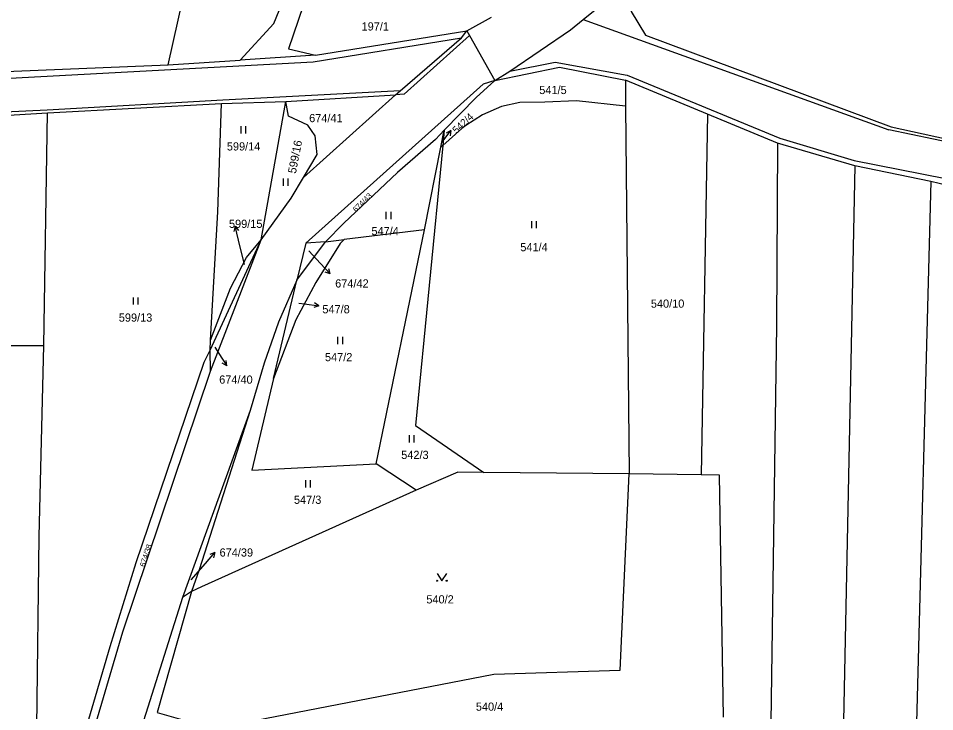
# Model space of a CAD drawing. Extents: x -747333 to -743907, y -1134120 to -1130051.
# Drawn here: x -746832.8 to -746642.5, y -1132407.1 to -1132263.2 of the extents above; entities that cross this region are included whole.
import ezdxf

# ---------------------------------------------------------------- set-up
doc = ezdxf.new("R2010")
doc.units = 0
for name, color, linetype in [('Hranice parcel', 7, 'Continuous'), ('Parcelní čísla', 7, 'Continuous'), ('Pop  PČ popisy', 7, 'Continuous'), ('Vnitřní kresba', 7, 'Continuous'), ('Značky kultur', 7, 'Continuous')]:
    doc.layers.add(name, color=color, linetype=linetype)

msp = doc.modelspace()

# ---------------------------------------------------------------- linework, layer by layer
at = {"layer": 'Hranice parcel'}
for p, q in [((-746801.64, -1132272.79), (-746795.83, -1132246.75)), ((-746779.69, -1132264.25), (-746775.72, -1132254.29)), ((-746786.69, -1132271.84), (-746779.69, -1132264.25)), ((-746739.61, -1132265.77), (-746734.54, -1132262.91)), ((-746771.04, -1132270.84), (-746739.61, -1132265.77)), ((-746801.64, -1132272.79), (-746786.69, -1132271.84)), ((-746771.04, -1132270.84), (-746786.69, -1132271.84)), ((-746841.63, -1132274.45), (-746801.64, -1132272.79)), ((-746706.71, -1132276.02), (-746706.66, -1132281.38)), ((-746689.65, -1132283.05), (-746706.71, -1132276.02)), ((-746777.2, -1132280.46), (-746754.45, -1132279.02)), ((-746773.55, -1132296.22), (-746754.45, -1132279.02)), ((-746826.69, -1132282.8), (-746790.54, -1132280.83)), ((-746790.54, -1132280.83), (-746777.2, -1132280.46)), ((-746782.33, -1132309.15), (-746777.2, -1132280.46)), ((-746706.66, -1132281.38), (-746716.86, -1132280.27)), ((-746706.66, -1132281.38), (-746705.91, -1132357.75)), ((-746843.01, -1132283.74), (-746826.69, -1132282.8)), ((-746827.45, -1132331.11), (-746826.69, -1132282.8)), ((-746689.65, -1132283.05), (-746690.96, -1132357.97)), ((-746675.12, -1132289.05), (-746689.65, -1132283.05)), ((-746745.05, -1132289.91), (-746744.33, -1132286.38)), ((-746744.33, -1132286.38), (-746744.64, -1132289.55)), ((-746659.11, -1132293.76), (-746675.12, -1132289.05)), ((-746744.64, -1132289.55), (-746750.3, -1132347.71)), ((-746748.42, -1132307.06), (-746745.05, -1132289.91)), ((-746744.64, -1132289.55), (-746745.05, -1132289.91)), ((-746643.27, -1132297.04), (-746659.11, -1132293.76)), ((-746628.68, -1132300.58), (-746643.27, -1132297.04)), ((-746748.42, -1132307.06), (-746765.08, -1132309.07)), ((-746758.43, -1132355.7), (-746748.42, -1132307.06)), ((-746792.94, -1132332.08), (-746782.33, -1132309.15)), ((-746792.84, -1132336.44), (-746782.33, -1132309.15)), ((-746774.96, -1132317.5), (-746768.96, -1132309.54)), ((-746773.04, -1132309.86), (-746774.96, -1132317.5)), ((-746768.96, -1132309.54), (-746773.04, -1132309.86)), ((-746768.96, -1132309.54), (-746765.08, -1132309.07)), ((-746765.08, -1132309.07), (-746765.92, -1132309.94)), ((-746779.77, -1132337.92), (-746774.96, -1132317.5)), ((-746775.12, -1132325.77), (-746779.77, -1132337.92)), ((-746843.71, -1132331.14), (-746827.45, -1132331.11)), ((-746792.94, -1132332.08), (-746792.82, -1132329.99)), ((-746792.84, -1132336.44), (-746792.94, -1132332.08)), ((-746779.77, -1132337.92), (-746784.26, -1132356.99)), ((-746784.62, -1132344.63), (-746798.7, -1132383.44)), ((-746750.3, -1132347.71), (-746736.09, -1132357.45)), ((-746784.26, -1132356.99), (-746758.43, -1132355.7)), ((-746750.15, -1132361.13), (-746758.43, -1132355.7)), ((-746705.91, -1132357.75), (-746736.09, -1132357.45)), ((-746690.96, -1132357.97), (-746705.91, -1132357.75)), ((-746687.18, -1132358.02), (-746690.96, -1132357.97)), ((-746686.33, -1132408.26), (-746687.18, -1132358.02)), ((-746796.79, -1132382.18), (-746803.91, -1132407.31)), ((-746796.79, -1132382.18), (-746798.7, -1132383.44))]:
    msp.add_line(p, q, dxfattribs=at)
for points in [[(-746770.48, -1132251.33), (-746776.66, -1132269.51), (-746771.04, -1132270.84)], [(-746733.81, -1132276.07), (-746730.72, -1132274.13), (-746718.09, -1132265.55), (-746715.48, -1132263.41), (-746712.32, -1132260.82), (-746705.52, -1132254.75)], [(-746705.52, -1132254.75), (-746705.52, -1132261.75), (-746702.56, -1132266.68), (-746651.51, -1132285.68), (-746635.38, -1132289.23)], [(-746754.45, -1132279.02), (-746753.49, -1132278.19), (-746740.77, -1132267.23), (-746739.61, -1132265.77)], [(-746739.61, -1132265.77), (-746739.07, -1132266.74), (-746733.81, -1132276.07)], [(-746733.81, -1132276.07), (-746720.42, -1132273.3), (-746706.71, -1132276.02)], [(-746733.81, -1132276.07), (-746736.22, -1132276.85), (-746773.04, -1132309.86)], [(-746744.33, -1132286.38), (-746737.69, -1132279.59), (-746733.81, -1132276.07)], [(-746792.82, -1132329.99), (-746791.31, -1132303.31), (-746790.54, -1132280.83)], [(-746773.55, -1132296.22), (-746770.72, -1132291.44), (-746771.15, -1132287.59), (-746772.66, -1132285.36), (-746776.66, -1132283.5), (-746777.2, -1132280.46)], [(-746716.86, -1132280.27), (-746723.47, -1132280.56), (-746728.62, -1132280.64), (-746732.43, -1132281.5), (-746736.35, -1132283.2), (-746739.81, -1132285.4), (-746740.67, -1132286.07), (-746744.64, -1132289.55)], [(-746744.33, -1132286.38), (-746746.11, -1132288.3), (-746754.04, -1132295.16), (-746765.17, -1132305.73), (-746768.96, -1132309.54)], [(-746675.12, -1132289.05), (-746675.34, -1132326.95), (-746676.51, -1132409.4), (-746678.81, -1132574.01), (-746679.52, -1132637.82), (-746680.95, -1132685.42)], [(-746659.11, -1132293.76), (-746661.68, -1132422.68), (-746664.25, -1132578.86), (-746666.03, -1132683.01)], [(-746782.33, -1132309.15), (-746776.08, -1132300.49), (-746773.55, -1132296.22)], [(-746643.27, -1132297.04), (-746646.55, -1132419.82), (-746647.69, -1132573.58), (-746650.17, -1132680.45)], [(-746792.82, -1132329.99), (-746788.68, -1132319.21), (-746785.4, -1132312.86), (-746782.33, -1132309.15)], [(-746765.92, -1132309.94), (-746771.01, -1132318.05), (-746775.12, -1132325.77)], [(-746774.96, -1132317.5), (-746778.75, -1132326.25), (-746781.68, -1132334.79), (-746784.62, -1132344.63)], [(-746829.39, -1132449.92), (-746828.42, -1132370.76), (-746827.45, -1132331.11)], [(-746829.39, -1132449.92), (-746822.67, -1132424.28), (-746813.68, -1132393.59), (-746808.27, -1132376.18), (-746794.14, -1132334.58), (-746792.94, -1132332.08)], [(-746829.59, -1132453.54), (-746811.05, -1132390.53), (-746792.84, -1132336.44)], [(-746784.62, -1132344.63), (-746795.21, -1132377.68), (-746796.79, -1132382.18)], [(-746803.91, -1132407.31), (-746792.28, -1132410.65), (-746734.05, -1132399.37), (-746707.78, -1132398.52), (-746705.91, -1132357.75)], [(-746736.09, -1132357.45), (-746741.5, -1132357.4), (-746750.15, -1132361.13)], [(-746750.15, -1132361.13), (-746794.71, -1132381.24), (-746796.79, -1132382.18)], [(-746798.7, -1132383.44), (-746811, -1132422.37), (-746816.39, -1132442.3)]]:
    msp.add_lwpolyline(points, dxfattribs=at)
at = {"layer": 'Pop  PČ popisy'}
for p, q in [((-746744.73, -1132288.88), (-746742.924, -1132286.483)), ((-746742.924, -1132286.483), (-746743.927, -1132286.982)), ((-746742.924, -1132286.483), (-746743.127, -1132287.584)), ((-746787.746, -1132306.338), (-746787.99, -1132307.431)), ((-746787.02, -1132309.25), (-746787.746, -1132306.338)), ((-746787.746, -1132306.338), (-746787.018, -1132307.189)), ((-746785.77, -1132314.26), (-746787.02, -1132309.25)), ((-746772.47, -1132311.47), (-746770.03, -1132314.05)), ((-746770.03, -1132314.05), (-746767.983, -1132316.245)), ((-746767.983, -1132316.245), (-746769.033, -1132315.854)), ((-746767.983, -1132316.245), (-746768.3, -1132315.171)), ((-746774.5, -1132322.29), (-746773.34, -1132322.46)), ((-746773.34, -1132322.46), (-746770.368, -1132322.878)), ((-746770.368, -1132322.878), (-746771.43, -1132323.234)), ((-746770.368, -1132322.878), (-746771.29, -1132322.242)), ((-746791.98, -1132331.44), (-746791.09, -1132332.79)), ((-746791.09, -1132332.79), (-746789.456, -1132335.307)), ((-746789.456, -1132335.307), (-746790.421, -1132334.74)), ((-746789.456, -1132335.307), (-746789.581, -1132334.194)), ((-746793.92, -1132376.36), (-746791.951, -1132374.095)), ((-746791.951, -1132374.095), (-746792.986, -1132374.522)), ((-746791.951, -1132374.095), (-746792.23, -1132375.179)), ((-746796.84, -1132379.78), (-746793.92, -1132376.36))]:
    msp.add_line(p, q, dxfattribs=at)
at = {"layer": 'Vnitřní kresba'}
for p, q in [((-746715.48, -1132263.41), (-746651.99, -1132286.34)), ((-746771.51, -1132272.22), (-746740.77, -1132267.23)), ((-746739.07, -1132266.74), (-746752.66, -1132278.93)), ((-746853.8, -1132276.58), (-746771.51, -1132272.22)), ((-746730.72, -1132274.13), (-746721.28, -1132272.26)), ((-746721.28, -1132272.26), (-746706.38, -1132274.95)), ((-746706.38, -1132274.95), (-746674.66, -1132288.06)), ((-746753.49, -1132278.19), (-746790.3, -1132280.16)), ((-746752.66, -1132278.93), (-746754.45, -1132279.02)), ((-746790.3, -1132280.16), (-746826.79, -1132282.23)), ((-746826.79, -1132282.23), (-746927.68, -1132287.24)), ((-746622.06, -1132292.55), (-746651.99, -1132286.34)), ((-746674.66, -1132288.06), (-746659.25, -1132292.71)), ((-746659.25, -1132292.71), (-746640.22, -1132296.44))]:
    msp.add_line(p, q, dxfattribs=at)
at = {"layer": 'Značky kultur'}
for p, q in [((-746786.501, -1132287.05), (-746786.501, -1132285.55)), ((-746785.5, -1132287.05), (-746785.5, -1132285.55)), ((-746777.721, -1132297.94), (-746777.721, -1132296.44)), ((-746776.72, -1132297.94), (-746776.72, -1132296.44)), ((-746756.351, -1132304.85), (-746756.351, -1132303.35)), ((-746755.35, -1132304.85), (-746755.35, -1132303.35)), ((-746726.171, -1132306.75), (-746726.171, -1132305.25)), ((-746725.17, -1132306.75), (-746725.17, -1132305.25)), ((-746808.851, -1132322.6), (-746808.851, -1132321.1)), ((-746807.85, -1132322.6), (-746807.85, -1132321.1)), ((-746766.401, -1132330.81), (-746766.401, -1132329.31)), ((-746765.4, -1132330.81), (-746765.4, -1132329.31)), ((-746751.561, -1132351.22), (-746751.561, -1132349.72)), ((-746750.56, -1132351.22), (-746750.56, -1132349.72)), ((-746773.091, -1132360.59), (-746773.091, -1132359.09)), ((-746772.09, -1132360.59), (-746772.09, -1132359.09))]:
    msp.add_line(p, q, dxfattribs=at)
msp.add_lwpolyline([(-746745.82, -1132378.459), (-746744.82, -1132379.96), (-746743.82, -1132378.459)], dxfattribs=at)
for centre in [(-746745.82, -1132379.959), (-746743.82, -1132379.959)]:
    msp.add_circle(centre, 0.1, dxfattribs=at)

# ---------------------------------------------------------------- texts
at = {"layer": 'Parcelní čísla'}
for s, p in [('197/1', (-746761.49, -1132265.69)), ('541/5', (-746724.593, -1132278.89)), ('674/41', (-746772.37, -1132284.73)), ('599/14', (-746789.46, -1132290.6)), ('599/15', (-746789.021, -1132306.68)), ('547/4', (-746759.44, -1132308.19)), ('541/4', (-746728.533, -1132311.53)), ('674/42', (-746766.97, -1132319.063)), ('540/10', (-746701.43, -1132323.25)), ('547/8', (-746769.63, -1132324.416)), ('599/13', (-746811.89, -1132326.15)), ('547/2', (-746769.09, -1132334.36)), ('674/40', (-746791.05, -1132339.023)), ('542/3', (-746753.253, -1132354.66)), ('547/3', (-746775.53, -1132363.98)), ('674/39', (-746790.97, -1132374.93)), ('540/2', (-746748.04, -1132384.66)), ('540/4', (-746737.76, -1132406.94))]:
    msp.add_text(s, height=1.7, dxfattribs=at).set_placement(p)
for s, height, rotation, p in [('542/4', 1.5, 43, (-746741.788, -1132287.218)), ('599/16', 1.7, 79, (-746775.135, -1132295.492)), ('674/43', 1.14, 45, (-746762.636, -1132303.503)), ('674/38', 1.14, 72, (-746806.507, -1132377.176))]:
    msp.add_text(s, height=height, rotation=rotation, dxfattribs=at).set_placement(p)

doc.saveas('drawing.dxf')
